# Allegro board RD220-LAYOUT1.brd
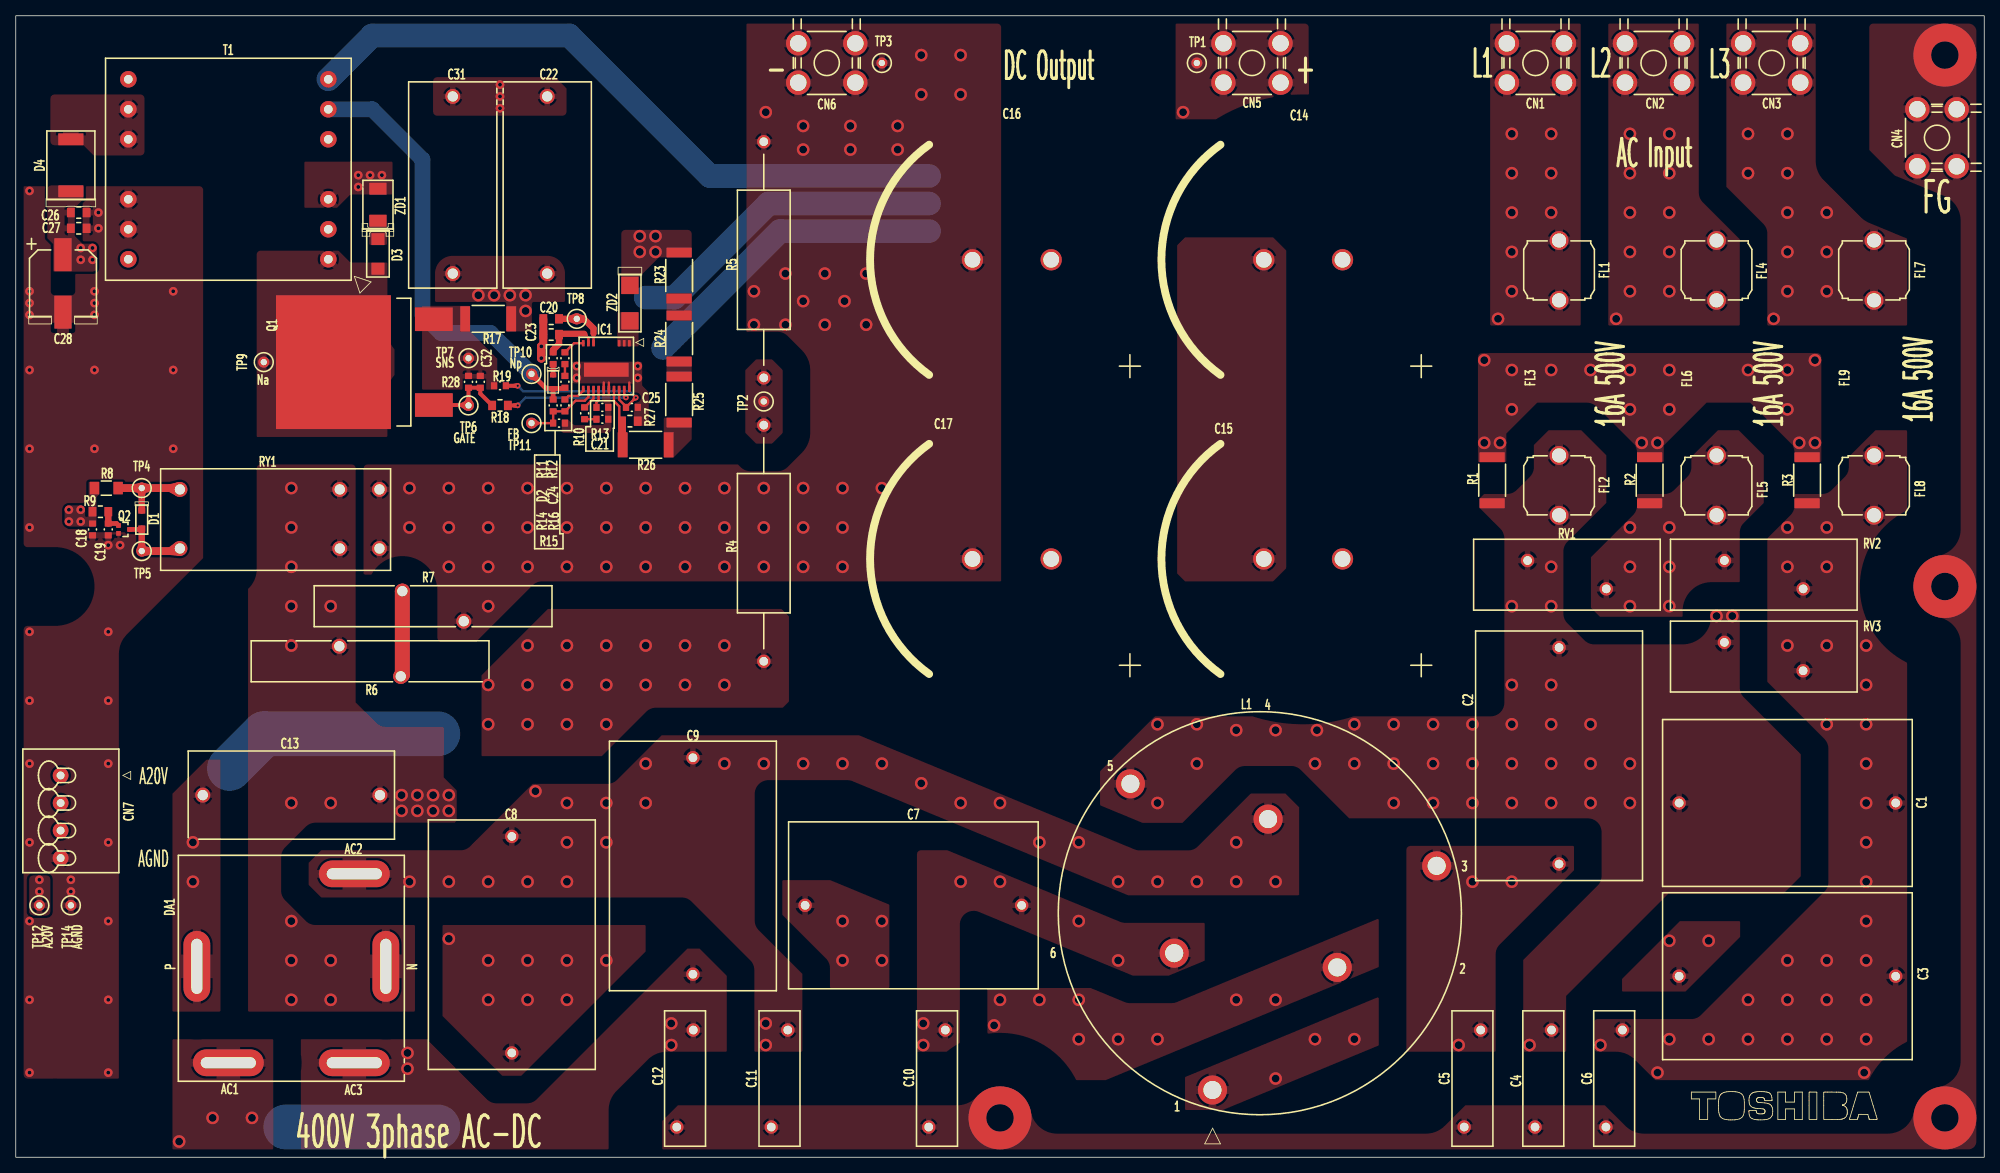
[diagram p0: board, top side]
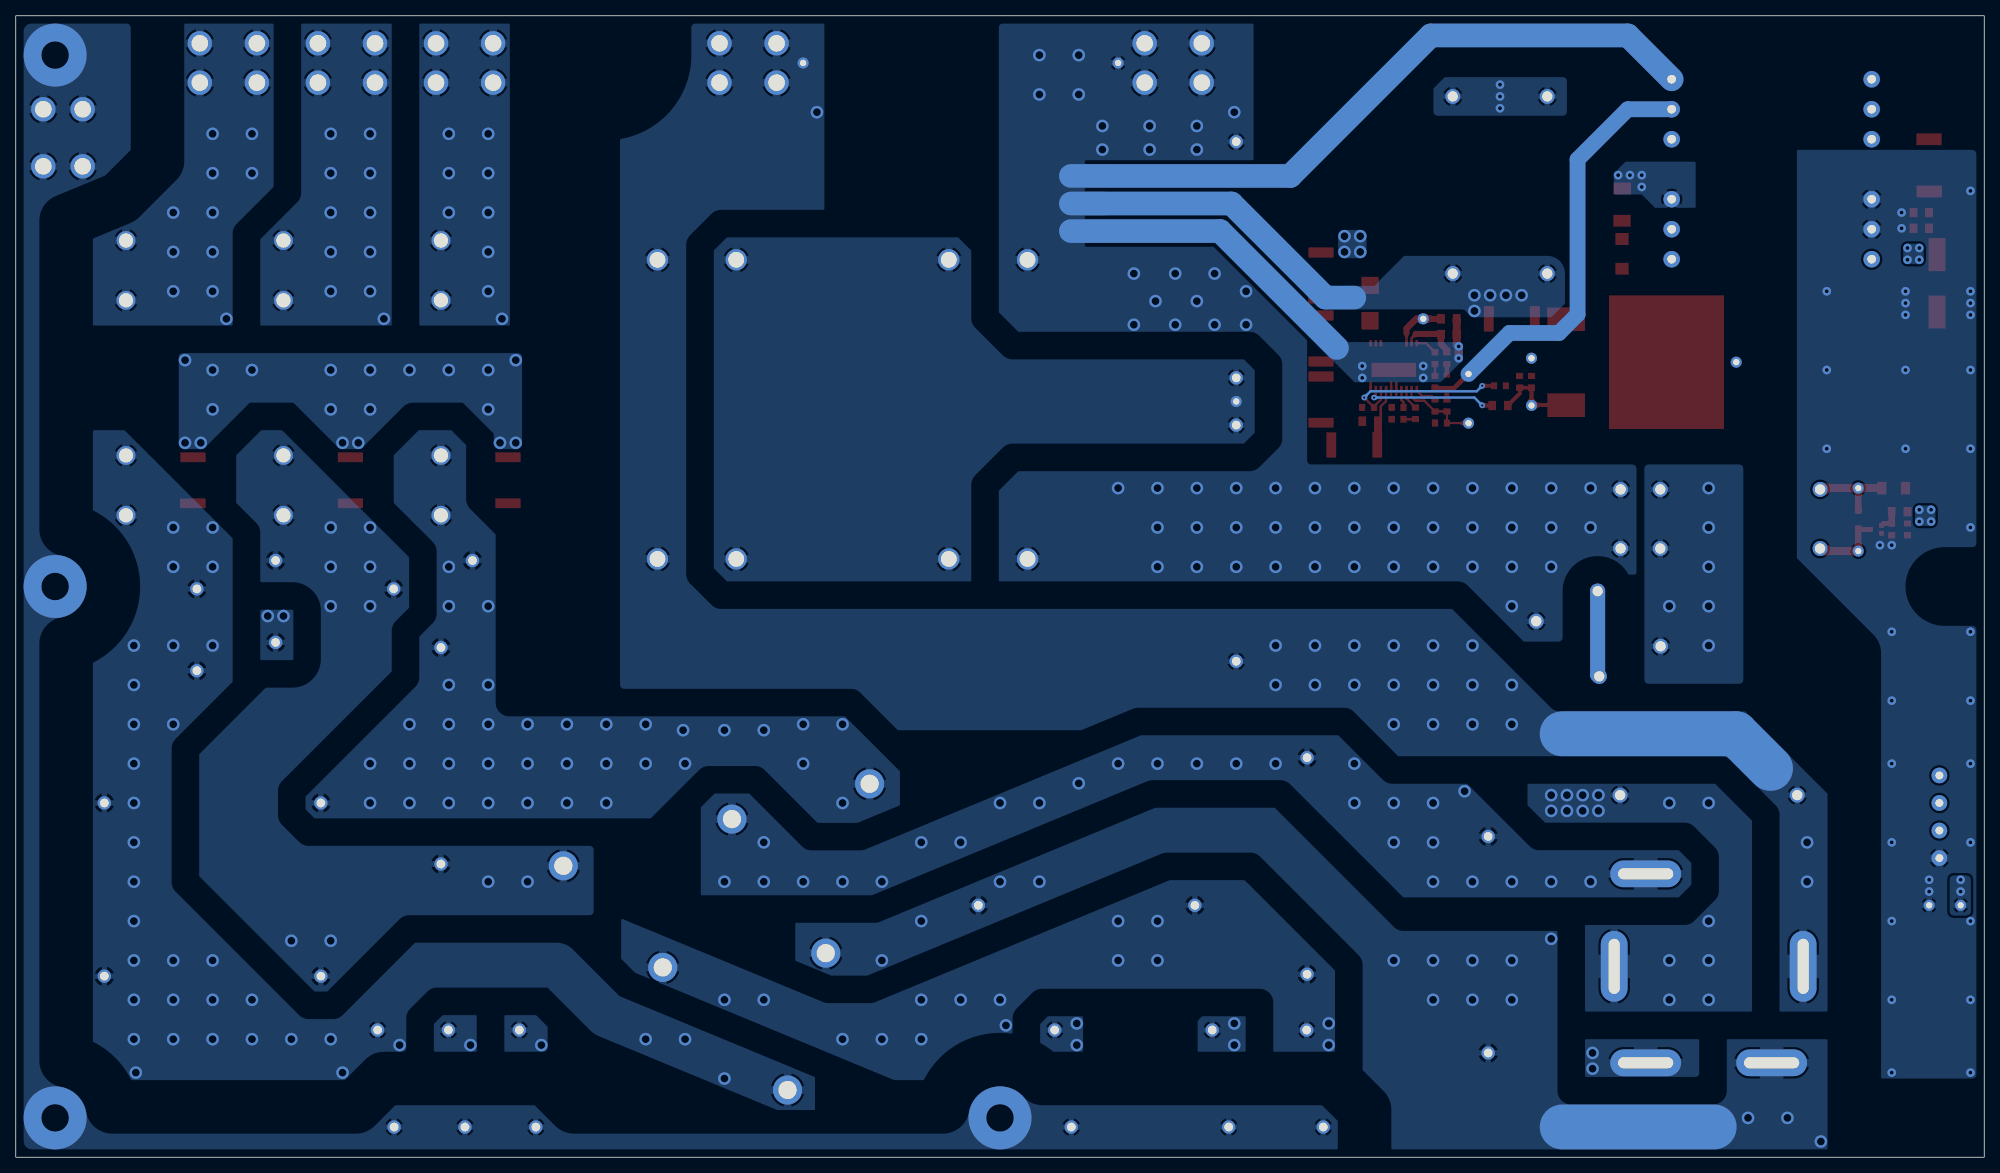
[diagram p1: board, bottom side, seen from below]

Outline 250 x 145 mm; copper layers: TOP, CONDUCTIVE2, CONDUCTIVE3, BOTTOM. Coordinates in mm from the lower left corner of the outline.
Outline path: rectangle 0,0 250,145

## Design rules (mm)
constraint set DEFAULT: 

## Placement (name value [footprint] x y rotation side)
C1  -  [TA_C0006DD]  225 45 180 top
C2  -  [TA_C0006DD]  196 51 90 top
C3  -  [TA_C0006DD]  225 23 180 top
C4  -  [TA_C0001DD]  194 10 90 top
C5  -  [TA_C0001DD]  185 10 90 top
C6  -  [TA_C0001DD]  203 10 90 top
C7  -  [TA_C0006DD]  114 32 0 top
C8  -  [TA_C0006DD]  63 27 270 top
C9  -  [TA_C0006DD]  86 37 90 top
C10  -  [TA_C0001DD]  117 10 90 top
C11  -  [TA_C0001DD]  97 10 90 top
C12  -  [TA_C0001DD]  85 10 90 top
C13  -  [TA_C0005DD]  35 46 180 top
C14  -  [TA_CE0001DD]  163.5 114 180 top
C15  -  [TA_CE0001DD]  163.5 76 180 top
C16  -  [TA_CE0001DD]  126.5 114 180 top
C17  -  [TA_CE0001DD]  126.5 76 180 top
C18  -  [TA_C0001RR]  9.75 79.75 90 top
C19  -  [TA_C0001RR]  11.75 79.75 90 top
C20  -  [TA_C0002RR]  68 106.5 0 top
C21  -  [TA_C0001RR]  74.5 93.75 180 top
C22  -  [TA_C0005DD]  67.5 123.5 90 top
C23  -  [TA_C0002RR]  68 104.5 0 top
C24  -  [TA_C0001RR]  69.75 98.5 270 top
C25  -  [TA_C0001RR]  78.25 95.25 180 top
C26  -  [TA_C0002RR]  8 120 180 top
C27  -  [TA_C0002RR]  8 118 180 top
C28  -  [TA_CE0002RR]  6 111 270 top
C31  -  [TA_C0005DD]  55.5 123.5 90 top
C32  -  [TA_C0001RR]  59 98.5 270 top
CN1  -  [TA_CN0004DD_OT_005_OT_006_]  193 139 90 top
CN2  -  [TA_CN0004DD_OT_005_OT_006_]  208 139 90 top
CN3  -  [TA_CN0004DD_OT_005_OT_006_]  223 139 90 top
CN4  -  [TA_CN0004DD_OT_005_OT_006_]  244 129.5 0 top
CN5  -  [TA_CN0004DD_OT_005_OT_006_]  157 139 90 top
CN6  -  [TA_CN0004DD_OT_005_OT_006_]  103 139 90 top
CN7  -  [TA_CN0002DD]  7 44 270 top
D1  -  [TA_D0002RR]  16 81 270 top
D2  -  [TA_D0001RR]  68.25 98.5 270 top
D3  -  [TA_D0005RR]  46 114.75 270 top
D4  -  [TA_D0006RR]  7 126 90 top
DA1  -  [TA_DA0001DD]  35 24 270 top
FL1  -  [TA_FL0001DD]  196 99 270 top
FL2  -  [TA_FL0001DD]  196 99 90 top
FL4  -  [TA_FL0001DD]  216 99 270 top
FL5  -  [TA_FL0001DD]  216 99 90 top
FL7  -  [TA_FL0001DD]  236 99 270 top
FL8  -  [TA_FL0001DD]  236 99 90 top
IC1  -  [TA_IC0002RR_70]  75 100.5 180 top
L1  -  [TA_L0001DD]  158 31 180 top
NOREF  -  []  5 5 0 top
NOREF#2  -  []  5 72.5 0 top
NOREF#3  -  []  175 140 0 top
NOREF#4  -  []  5 140 0 top
NOREF#5  -  []  212.8 4.8 0 top
Q1  -  [TA_FET0003RR]  44.5 101 90 top
Q2  -  [TA_Q0001RR]  13.75 79.75 270 top
R1  -  [TA_R0007RR]  187.5 86 270 top
R2  -  [TA_R0007RR]  207.5 86 270 top
R3  -  [TA_R0007RR]  227.5 86 270 top
R4  -  [TA_R0001DD]  95 78 270 top
R5  -  [TA_R0001DD]  95 114 270 top
R6  -  [TA_TH0001DD]  45 63 0 top
R7  -  [TA_TH0001DD]  53 70 0 top
R8  -  [TA_R0004RR]  11.5 85 0 top
R9  -  [TA_R0003RR]  10.75 82 180 top
R10  -  [TA_R0005RR]  72.25 94.5 270 top
R11  -  [TA_R0005RR]  68.25 101.5 270 top
R12  -  [TA_R0005RR]  69.75 101.5 90 top
R13  -  [TA_R0005RR]  74.5 95.25 0 top
R14  -  [TA_R0005RR]  68.25 95.5 270 top
R15  -  [TA_R0005RR]  69 93.25 0 top
R16  -  [TA_R0005RR]  69.75 95.5 90 top
R17  -  [TA_R0007RR]  60 106.5 0 top
R18  -  [TA_R0003RR]  61.5 95.5 0 top
R19  -  [TA_R0005RR]  61.5 98 0 top
R23  -  [TA_R0007RR]  84.25 112 270 top
R24  -  [TA_R0007RR]  84.25 104 270 top
R25  -  [TA_R0007RR]  84.25 96.25 270 top
R26  -  [TA_R0007RR]  80 90.5 180 top
R27  -  [TA_R0003RR]  78 93.5 0 top
R28  -  [TA_R0005RR]  57.5 98.5 90 top
RV1  -  [TA_RV0002DD]  197 74 180 top
RV2  -  [TA_RV0002DD]  222 74 180 top
RV3  -  [TA_RV0002DD]  222 63.6 180 top
RY1  -  [TA_RY0001DD]  33 81 0 top
T1  -  [TA_T0002DD]  27 125.5 90 top
TP1  -  [TA_TP0001DD]  150 139 0 top
TP2  -  [TA_TP0001DD]  95 96 0 top
TP3  -  [TA_TP0001DD]  110 139 0 top
TP4  -  [TA_TP0001DD]  16 85 90 top
TP5  -  [TA_TP0001DD]  16 77 90 top
TP6  -  [TA_TP0001DD]  57.5 95.5 180 top
TP7  -  [TA_TP0001DD]  57.5 101.5 180 top
TP8  -  [TA_TP0001DD]  71.25 106.5 180 top
TP9  -  [TA_TP0001DD]  31.5 101 90 top
TP10  -  [TA_TP0001DD]  65.5 99.5 180 top
TP11  -  [TA_TP0001DD]  65.5 93.25 180 top
TP12  -  [TA_TP0001DD]  3 32 90 top
TP14  -  [TA_TP0001DD]  7 32 90 top
ZD1  -  [TA_D0004RR]  46 121 90 top
ZD2  -  [TA_D0007RR]  78 108.5 270 top

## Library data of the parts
C1-C3 C7-C9 = PHE844RF7100MR30L2
C4-C6 C10-C12 = VKP472MCQEF0KR
C13 C22 C31 = PHE840EY7100MD16R06L2
C14-C17 = 400MXH1200MEFCSN35X60
C18 C19 = C1608X5R1V475K080AC
C20 C23 = GRM21BC71H475KE11L
C21 = C1608X7R1H224K080AE
C24 C32 = C1608C0G1H470J080AA
C25 = CGA3E2X7R1H102K080AA
C26 C27 = GRM21BR61H106ME43L
C28 = EMVH350ARA101MHA0G
CN1-CN6 = OT-005
CN7 = 1984989
D1 = CUS10F40_H3F
D2 = BAS516_L3F
D3 = US1M-E3/61T
D4 = VSSC520S-M3/57T
DA1 = VS-36MT120
FL1 FL2 FL4 FL5 FL7 FL8 = 8040.0001
IC1 = LT8316IFE*PBF
L1 = T60405S6123X317
Q1 = APT14M120S
Q2 = 2SC4738-Y_LF
R1-R3 = 3521220KFT
R4 R5 = ROX5SSJ56K
R6 R7 = SL32_5R020
R8 = ERJ8ENF62R0V
R9 = ERJ6ENF3301V
R10 R12 R28 = RK73H1JTTD1002D
R11 = RK73H1JTTD10R0F
R13 = RK73H1JTTD8202F
R14 = RK73H1JTTD2202F
R15 = RK73H1JTTD3001F
R16 = RK73H1JTTD1203F
R17 = RLP73N3AR068FTDF
R18 = RK73G2ATTD33R0F
R19 = RK73H1JTTD1000F
R23-R26 = CRGP2512F68K
R27 = ERJ6ENF6800V
RV1-RV3 = TND20SV821KB00AAA0
RY1 = RTH34024WG
T1 = 11328-T080
TP1-TP12 TP14 = Test_Land
ZD1 = SMBJ188D-M3/I
ZD2 = BZG03C200-M3-08

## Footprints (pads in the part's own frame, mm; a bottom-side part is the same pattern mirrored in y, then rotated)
TA_C0001DD
  round 1.7 hole 1.1: 1(-6.161,1.05) 2(6.161,-1.05)
TA_C0001RR
  custom 0.2x0.2 smd: 1(-0.75,0) 2(0.75,0)
TA_C0002RR
  custom 0.25x0.25 smd: 1(-1,0) 2(1,0)
TA_C0005DD
  round 1.9 hole 1.3: 1(-11.25,0) 2(11.25,0)
TA_C0006DD
  round 1.7 hole 1.1: 1(-13.75,0) 2(13.75,0)
TA_CE0001DD
  round 2.7 hole 2: 1(5,0) 2(-5,0)
TA_CE0002RR
  custom 0.55x0.55 smd: 1(3.65,0) 2(-3.65,0)
TA_CN0002DD
  round 2 hole 1: 1(-4.5,-1.3) 2(-1,-1.3) 3(2.5,-1.3) 4(6,-1.3)
TA_CN0004DD_OT_005_OT_006_
  round 3.1 hole 2.1: 1(-2.5,-3.625) 2(2.5,-3.625) 3(2.5,3.625) 4(-2.5,3.625)
TA_D0001RR
  custom 0.15x0.15 smd: A(0.85,0) C(-0.85,0)
TA_D0002RR
  custom 0.2x0.2 smd: A(1.15,0) C(-1.15,0)
TA_D0004RR
  custom 0.38x0.38 smd: A(2.035,0) C(-2.035,0)
TA_D0005RR
  custom 0.38x0.38 smd: A(1.88,0) C(-1.88,0)
TA_D0006RR
  custom 0.38x0.38 smd: A(3.305,0) C(-3.305,0)
TA_D0007RR
  custom 0.55x0.55 smd: A(2.25,0) C(-2.25,0)
TA_DA0001DD
  oval 3.4x9 hole 1.4x7: AC1(12,-8) AC2(-12,8) AC3(12,8)
  oval 9x3.4 hole 7x1.4: N(-0.25,12) P(-0.25,-12)
TA_FET0003RR
  custom 3.65x3.65 smd: D(0,4.15)
  custom 0.75x0.75 smd: G(-5.45,-8.6) S(5.45,-8.6)
TA_FL0001DD
  round 2.4 hole 1.8: 1(-17.45,0) 2(-9.85,0)
TA_IC0002RR_70
  custom 0.087x0.087 smd: 1(-2.925,-2.9) 2(-2.275,-2.9) 3(-1.625,-2.9) 8(1.625,-2.9) 9(2.275,-2.9) 10(2.925,-2.9) 11(2.925,2.9) 12(2.275,2.9) 13(1.625,2.9) 14(0.975,2.9) 15(0.325,2.9) 16(-0.325,2.9) 17(-0.975,2.9) 18(-1.625,2.9) 19(-2.275,2.9) 20(-2.925,2.9)
  custom 0.445x0.445 smd: 21(0,0.47)
TA_L0001DD
  round 3.7 hole 2.3: 1(6.018,22.458) 2(-9.83,6.883) 3(-22.458,-6.018) 4(-1.046,-11.954) 5(16.44,-16.44) 6(10.876,5.071)
TA_Q0001RR
  custom 0.15x0.15 smd: B(-0.5,-0.7) C(0,0.7) E(0.5,-0.7)
TA_R0001DD
  round 1.7 hole 1.1: 1(-15,0) 2(15,0)
TA_R0003RR
  custom 0.25x0.25 smd: 1(-1,0) 2(1,0)
TA_R0004RR
  custom 0.3x0.3 smd: 1(-1.5,0) 2(1.5,0)
TA_R0005RR
  custom 0.2x0.2 smd: 1(-0.75,0) 2(0.75,0)
TA_R0007RR
  custom 0.312x0.312 smd: 1(-2.925,0) 2(2.925,0)
TA_RV0002DD
  round 1.7 hole 1.1: 1(-5,1.8) 2(5,-1.8)
TA_RY0001DD
  round 1.9 hole 1.3: 11-1(8.15,3.83) 11-2(8.15,-3.67) 14-1(13.19,3.83) 14-2(13.19,-3.67) A1(-12.15,3.83) A2(-12.15,-3.67)
TA_T0002DD
  round 2.1 hole 1.1: 1(-11.43,-12.7) 2(-7.62,-12.7) 3(-3.81,-12.7) 4(3.81,-12.7) 5(7.62,-12.7) 6(11.43,-12.7) 7(11.43,12.7) 8(7.62,12.7) 9(3.81,12.7) 10(-3.81,12.7) 11(-7.62,12.7) 12(-11.43,12.7)
TA_TH0001DD
  round 1.9 hole 1.3: 1(-3.9,1.91) 2(3.9,-1.91)
TA_TP0001DD
  round 1.4 hole 0.8: 1(0,0)

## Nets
GND_A: C18.1 C19.1 C26.1 C27.1 C28.1 CN7.4 Q2.E T1.10 T1.11 TP14.1
GND_DC: C16.1 C17.1 C20.1 C21.1 C22.1 C23.1 C25.1 C31.1 CN6.1 CN6.2 CN6.3 CN6.4 IC1.15 IC1.16 IC1.20 IC1.21 R5.1 R7.2 R13.2 R15.2 R17.2 R27.2 RY1.14-1 RY1.14-2 T1.6 TP3.1
GND_F: C4.1 C5.1 C6.1 C10.1 C11.1 C12.1 CN4.1 CN4.2 CN4.3 CN4.4
VDD20_A: C18.2 C26.2 C27.2 C28.2 CN7.1 D4.C R8.1 R9.2 TP12.1
L1: CN1.1 CN1.2 CN1.3 CN1.4 FL1.1 FL1.2
L1F: C1.2 C2.2 C4.2 FL2.1 FL2.2 L1.5 R1.2 RV1.2 RV3.2
L1R: C7.2 C8.2 C10.2 DA1.AC1 L1.6
L2: CN2.1 CN2.2 CN2.3 CN2.4 FL4.1 FL4.2
L2F: C2.1 C3.2 C5.2 FL5.1 FL5.2 L1.3 R2.2 RV1.1 RV2.2
L2R: C8.1 C9.2 C11.2 DA1.AC2 L1.4
L3: CN3.1 CN3.2 CN3.3 CN3.4 FL7.1 FL7.2
L3F: C1.1 C3.1 C6.2 FL8.1 FL8.2 L1.1 R3.2 RV2.1 RV3.1
L3R: C7.1 C9.1 C12.2 DA1.AC3 L1.2
M: C14.1 C15.1 C16.2 C17.2 R4.1 R5.2 TP2.1
RDIS: R1.1 R2.1 R3.1
SIGN0021: C20.2 IC1.8 TP8.1
SIGN0023: IC1.13 R10.1
SIGN0024: C21.2 R10.2
SIGN0029: C23.2 IC1.9 R11.1
SIGN00121: R6.2 R7.1
SIGN00122: C13.1 DA1.N R6.1 RY1.11-1 RY1.11-2
SIGN00123: D1.C R8.2 RY1.A1 TP4.1
SIGN00124: D1.A Q2.C RY1.A2 TP5.1
SIGN00125: C19.2 Q2.B R9.1
SIGN00210: D2.C R11.2
SIGN00211: C24.2 D2.A R14.1 T1.5 TP10.1
SIGN00212: IC1.10 R12.2
SIGN00213: C24.1 R12.1
SIGN00214: IC1.14 R13.1
SIGN00218: IC1.11 R16.2
SIGN00219: IC1.12 R14.2 R15.1 R16.1 TP11.1
SIGN00220: C32.1 Q1.S R17.1 R19.1 R28.2 TP7.1
SIGN00222: IC1.19 R18.2
SIGN00223: C25.2 IC1.18 R19.2
SIGN00224: D3.C ZD1.C
SIGN00225: D3.A Q1.D T1.1 TP9.1
SIGN00226: C32.2 Q1.G R18.1 R28.1 TP6.1
SIGN00227: D4.A T1.8 T1.9
SIGN00230: IC1.1 IC1.2 IC1.3 ZD2.A
SIGN00231: R25.2 R26.1
SIGN00232: R23.2 R24.1
SIGN00233: R24.2 R25.1
SIGN00234: IC1.17 R26.2 R27.1
VP_DC: C13.2 C14.2 C15.2 C22.2 C31.2 CN5.1 CN5.2 CN5.3 CN5.4 DA1.P R4.2 R23.1 T1.3 TP1.1 ZD1.A ZD2.C

Pads without a net: CN7 2 3; T1 2 4 7 12

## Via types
v1: diameter 0.7, hole 0.3, TOP to BOTTOM, 4 vias
v2: diameter 1.6, hole 1, TOP to BOTTOM, 305 vias
v3: diameter 1.1, hole 0.5, TOP to BOTTOM, 58 vias
v4: diameter 8, hole 3.5, TOP to BOTTOM, 4 vias

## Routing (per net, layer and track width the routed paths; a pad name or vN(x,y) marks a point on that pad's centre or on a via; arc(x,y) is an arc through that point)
GND_A:
  vias: v3(1.75,122.75) v3(1.75,110) v3(1.75,108.5) v3(1.75,107) v3(1.75,100) v3(1.75,90) v3(1.75,80) v3(1.75,66.75) v3(1.75,58) v3(1.75,50) v3(1.75,40) v3(1.75,30) v3(1.75,20) v3(1.75,10.75) v3(7,35.25) v3(7,33.75) v3(10,110) v3(10,108.5) v3(10,107) v3(10,100) v3(10,90) v3(10.5,120) v3(10.5,118) v3(11.75,77.75) v3(11.75,66.75) v3(11.75,58) v3(11.75,50) v3(11.75,40) v3(11.75,30) v3(11.75,20) v3(11.75,10.75) v3(13.25,77.75) v3(20,110) v3(20,100) v3(20,90)
GND_DC: length 176
  TOP w0.3: 74.67,96.8 IC1.15 74.67,98.4 ; 75.33,98.4 IC1.16 75.33,96.8 ; IC1.20 77.92,98.4
  TOP w1: C20.1 C23.1 67,103.25 v3(66.75,103)
  TOP w1.1: v3(66.75,101.5) v3(66.75,103)
  BOTTOM w3: 82.2,102.8 97.05,117.65 116,117.65 ; 80,109.2 83.65,109.2 95.6,121.15 116,121.15 ; T1.6 45.27,142.5 70.29,142.5 88.14,124.65 116,124.65
  vias: v2(50,85) v2(50,80) v2(55,85) v2(55,80) v2(55,75) v2(58.75,109.5) v2(60,85) v2(60,80) v2(60,75) v2(60,70) v2(60.75,109.5) v2(62.75,109.5) v2(64.75,109.5) v2(64.75,107.5) v2(65,85) v2(65,80) v2(65,75) v2(70,85) v2(70,80) v2(70,75) v2(75,85) v2(75,80) v2(75,75) v2(80,85) v2(80,80) v2(80,75) v2(85,85) v2(85,80) v2(85,75) v2(90,85) v2(90,80) v2(90,75) v2(93.75,110) v2(93.75,105.75) v2(95,85) v2(95,80) v2(95,75) v2(95.25,132.75) v2(97.75,112.25) v2(97.75,105.75) v2(100,131) v2(100,128) v2(100,108.75) v2(100,85) v2(100,80) v2(100,75) v2(102.75,112.25) v2(102.75,105.75) v2(105,85) v2(105,80) v2(105,75) v2(105.25,108.75) v2(106,131) v2(106,128) v2(108,112.25) v2(108,105.75) v2(110,85) v2(112,131) v2(112,128) v2(115,140) v2(115,135) v2(120,140) v2(120,135) v3(71.25,100.5) v3(71.25,99) v3(79,100.5) v3(79,99)
GND_F:
  vias: v4(125,5) v4(245,140) v4(245,72.5) v4(245,5)
VDD20_A: length 75.9
  CONDUCTIVE3 w1.5: 8.1,83.89 8.1,112.36 ; 3.85,36.66 3.85,46.65 CN7.1 5.7,63.94 11.55,69.79 11.55,75.21 7.49,79.27
  vias: v3(3,35.25) v3(3,33.75) v3(6.75,82.25) v3(6.75,80.75) v3(8.25,115.5) v3(8.25,114) v3(8.25,82.25) v3(8.25,80.75) v3(9.75,115.5) v3(9.75,114)
L1:
  vias: v2(188.25,106.5) v2(190,130) v2(190,125) v2(190,120) v2(190,115) v2(190,110) v2(195,130) v2(195,125) v2(195,120)
L1F:
  vias: v2(145,55) v2(145,45) v2(150,55) v2(150,50) v2(155,54.25) v2(160,54.25) v2(165,50) v2(165.25,54.25) v2(170,55) v2(170,50) v2(175,55) v2(175,50) v2(175,45) v2(180,55) v2(180,50) v2(180,45) v2(185,55) v2(185,50) v2(185,45) v2(190,70) v2(190,60) v2(190,55) v2(190,50) v2(190,45) v2(192.25,14.25) v2(195,75) v2(195,70) v2(195,60) v2(195,55) v2(195,50) v2(195,45) v2(200,55) v2(200,50) v2(200,45) v2(205,50) v2(205,45) v2(216,68.75) v2(218,68.75)
L1R: length 38.4
  CONDUCTIVE3 w5.7: 34.5,3.85 53.6,3.85
  BOTTOM w5.7: 34.3,3.85 53.6,3.85
  vias: v2(20.75,2) v2(25,5) v2(30,5) v2(55,27.75) v2(60,25) v2(60,20) v2(65,25) v2(65,20) v2(70,25) v2(70,20) v2(75,25) v2(115.25,17) v2(115.25,14.25) v2(120,35) v2(125,35) v2(135,30) v2(140,25)
L2:
  vias: v2(203.25,106.5) v2(205,130) v2(205,125) v2(205,120) v2(205,115) v2(205,110) v2(210,130) v2(210,125) v2(210,120) v2(210,115) v2(210,110)
L2F:
  vias: v2(183.25,14.25) v2(185,35) v2(190,35) v2(205,80) v2(205,75) v2(205,70) v2(210,80) v2(210,75) v2(210,70) v2(210,27.5) v2(215,27.5)
L2R:
  vias: v2(50,35) v2(55,35) v2(60,35) v2(65,35) v2(66,46.5) v2(70,45) v2(70,40) v2(70,35) v2(75,45) v2(75,40) v2(80,50) v2(80,45) v2(90,50) v2(95,50) v2(95.25,17) v2(95.25,14.25) v2(100,50) v2(105,50) v2(110,50) v2(115,47.5) v2(120,45) v2(125,45) v2(130,40) v2(135,40) v2(140,35) v2(145,35) v2(150,35) v2(155,40) v2(155,35) v2(160,35)
L3:
  vias: v2(220,130) v2(220,125) v2(223.25,106.5) v2(225,130) v2(225,125) v2(225,120) v2(225,115) v2(225,110) v2(230,120) v2(230,115) v2(230,110)
L3F:
  vias: v2(160,10) v2(165,15) v2(170,15) v2(201.25,14.25) v2(208.5,10.75) v2(210,15) v2(215,15) v2(220,20) v2(220,15) v2(225,80) v2(225,75) v2(225,65) v2(225,25) v2(225,20) v2(225,15) v2(230,80) v2(230,75) v2(230,65) v2(230,55) v2(230,25) v2(230,20) v2(230,15) v2(234.75,10.75) v2(235,65) v2(235,60) v2(235,55) v2(235,50) v2(235,45) v2(235,40) v2(235,35) v2(235,30) v2(235,25) v2(235,20) v2(235,15)
L3R:
  vias: v2(49.75,13.25) v2(49.75,11.25) v2(83.25,17) v2(83.25,14.25) v2(105,30) v2(105,25) v2(110,30) v2(110,25) v2(124.25,16.75) v2(125,20) v2(130,20) v2(135,20) v2(135,15) v2(140,15) v2(145,15) v2(155,20) v2(160,20)
RDIS:
  vias: v2(186.5,101.25) v2(186.5,90.75) v2(188.5,90.75) v2(190,100) v2(190,95) v2(195,100) v2(200,100) v2(205,100) v2(205,95) v2(206.5,90.75) v2(208.5,90.75) v2(210,100) v2(210,95) v2(220,100) v2(225,100) v2(225,95) v2(226.5,90.75) v2(228.5,101.25) v2(228.5,90.75)
SIGN0021: length 6.8
  TOP w0.3: IC1.8 73.38,104.72
  TOP w0.8: 73.38,104.72 73.38,105.28 72.15,106.5 TP8.1 C20.2
SIGN0023: length 2.8
  TOP w0.3: R10.1 73.38,96.38 IC1.13
SIGN0024: length 1.5
  TOP w0.3: R10.2 C21.2
SIGN0029: length 7.3
  TOP w0.3: IC1.9 72.72,104.05 72.17,104.6
  TOP w0.8: 72.17,104.6 69,104.6 C23.2 69,103.31 68.25,102.56 R11.1
SIGN00121: length 43.6
  TOP w1.9: R6.2 49.1,61.29 R7.1
  CONDUCTIVE2 w1.9: R6.2 49.1,61.29 R7.1
  CONDUCTIVE3 w1.9: R7.1 49.1,61.29 R6.2
  BOTTOM w1.9: R6.2 49.1,61.29 R7.1
SIGN00122:
  vias: v2(35,85) v2(35,80) v2(35,75) v2(35,70) v2(35,65) v2(35,45) v2(35,30) v2(35,25) v2(35,20) v2(40,70) v2(40,45) v2(40,25) v2(40,20) v2(49,46) v2(49,44) v2(51,46) v2(51,44) v2(53,46) v2(53,44) v2(55,46) v2(55,44)
SIGN00123: length 10.7
  TOP w0.8: D1.C TP4.1
  TOP w1: R8.2 TP4.1 19.63,85 RY1.A1
SIGN00124: length 9.3
  TOP w0.6: D1.A 15.9,79.75 Q2.C
  TOP w0.8: D1.A TP5.1
  TOP w1: TP5.1 19.66,77 RY1.A2
SIGN00125: length 2.9
  TOP w0.6: Q2.B 12.8,80.5 C19.2
  TOP w0.8: C19.2 R9.1
SIGN00210: length 1.4
  TOP w0.6: R11.2 D2.C
SIGN00211: length 57.7
  TOP w0.6: C24.2 69.65,97.65 D2.A ; R14.1 D2.A ; D2.A 67.35,97.65 TP10.1
  BOTTOM w2: T1.5 45.27,133.12 51.65,126.74 51.65,107.06 54.01,104.7 60.3,104.7 TP10.1
SIGN00212: length 2.8
  TOP w0.3: R12.2 70.9,103.4 IC1.10
SIGN00213: length 1.5
  TOP w0.3: C24.1 R12.1
SIGN00214: length 2.5
  TOP w0.3: IC1.14 74.03,96.18 73.75,95.9 R13.1
SIGN00218: length 3
  TOP w0.3: IC1.11 72.08,97.38 71.39,96.7 70.2,96.7 R16.2
SIGN00219: length 10.5
  TOP w0.3: TP11.1 R15.1 R14.2 R16.1 71.1,96.1 72.25,96.1 72.72,96.57 IC1.12
SIGN00222: length 16.6
  TOP w0.3: v1(77.5,96.5) 77.28,96.9 IC1.19
  TOP w0.5: R18.2 v1(63.75,95.5)
  BOTTOM w0.3: v1(63.75,95.5) 64.75,96.5 v1(77.5,96.5)
SIGN00223: length 21.6
  TOP w0.3: IC1.18 76.62,96.24 77.5,95.37 C25.2 v1(78.75,96.5)
  TOP w0.5: R19.2 v1(63.75,98)
  BOTTOM w0.3: v1(78.75,96.5) 77.95,97.3 64.45,97.3 v1(63.75,98)
SIGN00226: length 11
  TOP w0.5: R18.1 59,97 C32.2 R28.1 TP6.1 56.59,95.55 Q1.G
SIGN00234: length 7.6
  TOP w0.3: IC1.17 75.97,96.05 76.65,95.37 76.65,93.85 R27.1
  TOP w1: R26.2 77,90.58 R27.1
VP_DC: length 197.6
  CONDUCTIVE2 w3: 85.05,118.6 117.19,118.6 120.44,121.85 150,121.85 ; 150,125.35 118.99,125.35 115.74,122.1 75.15,122.1
  CONDUCTIVE3 w5.7: 52.2,53.79 31.54,53.79 27.14,49.39
  BOTTOM w5.7: 53.6,53.79 31.54,53.79 27.14,49.39
  vias: v2(22.5,40) v2(22.5,35) v2(60,60) v2(60,55) v2(65,65) v2(65,60) v2(65,55) v2(70,65) v2(70,60) v2(70,55) v2(75,65) v2(75,60) v2(75,55) v2(79.25,117) v2(79.25,115) v2(80,65) v2(80,60) v2(81.25,117) v2(81.25,115) v2(85,65) v2(85,60) v2(90,65) v2(90,60) v2(148.25,132.75) v3(43.5,124.75) v3(43.5,123.25) v3(45,124.75) v3(46.5,124.75) v3(61.5,136.25) v3(61.5,134.75) v3(61.5,133.25)

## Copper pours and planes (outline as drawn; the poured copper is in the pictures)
GND_A on TOP: 3.7,116.81 3.73,116.64 3.83,116.49 4.41,115.92 4.44,115.87 4.45,115.81 4.45,110 4.6,109.65 4.95,109.5 7.05,109.5 7.4,109.65 7.55,110 7.55,112.05 7.59,112.16 7.7,112.2 9.8,112.2 10.37,112.43 10.6,113 10.6,115.5 10.35,116.1 9.75,116.35 8.66,116.35 8.61,116.36 8.56,116.39 8.54,116.41 8.51,116.46 8.5,116.51 8.5,121.11 8.51,121.17 8.54,121.22 8.77,121.44 8.87,121.59 8.9,121.76 8.9,123.2 8.94,123.31 9.05,123.35 23.3,123.35 23.65,123.2 23.8,122.85 23.8,76.17 23.79,76.11 23.76,76.06 14.1,66.4 13.71,65.95 13.42,65.44 13.22,64.88 13.11,64.3 13.1,64 13.1,10.14 13.06,10.03 12.95,9.99 5.32,9.99 5,10 4.68,9.99 1.5,9.99 1.25,10.06 1.07,10.24 1,10.49 1,67 1.07,67.25 1.25,67.43 1.5,67.5 5,67.5 10,72.5 5,77.5 1.5,77.5 1.15,77.65 1,78 1,123.2 1.04,123.31 1.15,123.35 3.58,123.35 3.7,123.29 3.73,123.16 3.71,123.06 3.7,122.95 ; 32 cut-outs
GND_A on BOTTOM: 1.5,77.5 1.25,77.57 1.07,77.75 1,78 1,127.46 1.07,127.71 1.25,127.89 1.5,127.96 23.65,127.96 23.76,127.92 23.8,127.81 23.8,76.17 23.79,76.11 23.76,76.06 14.1,66.4 13.36,65.3 13.1,64 13.1,10.15 13.06,10.04 12.95,10 1.5,10 1.25,10.07 1.07,10.25 1,10.5 1,67 1.07,67.25 1.25,67.43 1.5,67.5 5,67.5 10,72.5 5,77.5 ; 27 cut-outs
GND_A on CONDUCTIVE2: 1.5,77.5 1.25,77.57 1.07,77.75 1,78 1,127.46 1.07,127.71 1.25,127.89 1.5,127.96 23.65,127.96 23.76,127.92 23.8,127.81 23.8,76.17 23.79,76.11 23.76,76.06 14.1,66.4 13.36,65.3 13.1,64 13.1,10.15 13.06,10.04 12.95,10 5.11,10 5,10 4.89,10 1.5,10 1.25,10.07 1.07,10.25 1,10.5 1,67 1.07,67.25 1.25,67.43 1.5,67.5 5,67.5 10,72.5 5,77.5 ; 27 cut-outs
GND_A on CONDUCTIVE3: 1,67 1.07,67.25 1.25,67.43 1.5,67.5 5,67.5 10,72.5 5,77.5 1.5,77.5 1.25,77.57 1.07,77.75 1,78 1,127.46 1.07,127.71 1.25,127.89 1.5,127.96 23.65,127.96 23.76,127.92 23.8,127.81 23.8,76.17 23.79,76.11 23.76,76.06 14.1,66.4 13.36,65.3 13.1,64 13.1,10.15 13.06,10.04 12.95,10 1.15,10 1.04,10.04 1,10.15 ; 20 cut-outs
GND_DC on TOP: 100.9,99.94 100.62,101.33 99.83,102.52 98.57,103.78 98.01,104.34 97.44,104.72 96.78,104.85 93.3,104.85 93.14,104.84 92.98,104.82 92.85,104.85 92.8,104.97 92.8,143.85 92.84,143.96 92.95,144 124.65,144 125,143.85 125.15,143.5 125.15,73.3 125.11,73.19 125,73.15 66.86,73.15 66.19,73.02 65.62,72.64 58.53,65.54 58.48,65.51 58.42,65.5 54.05,65.5 53.7,65.65 53.55,66 53.55,71.91 51.9,75.37 48.17,76.26 46.99,75.83 45.99,75.09 45.56,74.61 45.21,74.08 45.16,74.02 45.08,74 44.5,74 44.37,74.02 44.24,74.07 44.19,74.13 44.17,74.2 44.17,87.5 44.24,87.75 44.42,87.93 44.67,88 91.66,88 91.72,87.99 91.77,87.96 92.31,87.46 92.58,87.3 92.73,87.25 93.09,87.16 93.3,87.15 96.77,87.15 97.44,87.28 98.01,87.66 98.57,88.22 99.83,89.48 100.62,90.67 100.9,92.06 ; 44 cut-outs
GND_DC on TOP: 69.6,92 69.47,92.03 69.38,92.12 69.35,92.25 69.35,93.55 69.39,93.66 69.5,93.7 70.09,93.7 70.15,93.69 70.19,93.66 70.7,93.15 70.93,93.02 71.06,93 74.6,93 74.85,93.25 74.85,95.7 74.52,96.03 74.48,96.09 74.47,96.15 74.47,96.18 74.47,96.75 74.52,96.86 74.62,96.9 75.38,96.9 75.48,96.86 75.53,96.75 75.53,96.05 75.55,95.9 75.64,95.73 75.65,95.68 75.65,92.5 75.58,92.25 75.4,92.07 75.15,92
GND_DC on TOP: 53.25,112.19 53.25,112.2 53.91,113.84 55.55,114.5 55.56,114.5 67.44,114.5 67.45,114.5 69.09,113.84 69.75,112.2 69.75,112.19 69.75,108.8 69.71,108.69 69.6,108.65 65.8,108.65 65.67,108.62 65.58,108.53 65.55,108.4 65.55,105.05 65.51,104.94 65.4,104.9 62.45,104.9 62.34,104.94 62.3,105.05 62.3,108.4 62.23,108.58 62.05,108.65 53.4,108.65 53.29,108.69 53.25,108.8 ; 8 cut-outs
GND_DC on TOP: 78.65,92.9 78.54,92.94 78.5,93.05 78.5,94.64 78.51,94.7 78.54,94.74 78.6,94.8 78.6,95.65 78.61,95.71 78.67,95.78 78.71,95.8 78.96,95.88 79.38,96.67 78.63,97.14 78.5,97.17 78.45,97.29 78.45,97.95 78.4,98.12 78.28,98.25 78.1,98.3 70.95,98.3 70.83,98.33 70.73,98.42 70.7,98.55 70.7,100.9 70.74,101.01 70.85,101.05 79.3,101.05 79.42,101.02 79.52,100.92 79.55,100.8 79.55,98.03 80.36,97.23 80.39,97.18 80.4,97.12 80.4,93.05 80.36,92.94 80.25,92.9
GND_DC on BOTTOM: 66.24,101.29 66.2,101.5 66.2,103 66.36,103.39 66.75,103.55 80.83,103.55 82.28,105 82.39,105.05 82.5,105 84.41,103.09 84.45,102.99 84.41,102.88 80.02,98.49 79.97,98.46 79.91,98.45 69.25,98.45 69.04,98.49 68.86,98.61
GND_DC on BOTTOM: outline of 105 points within 44.17,65.5 125.15,144 ; 44 cut-outs
GND_DC on BOTTOM: 73.61,114.5 73.66,114.49 73.71,114.46 77.47,110.7 81,110.7 81.25,110.63 81.43,110.45 81.5,110.2 81.5,108.2 81.36,107.85 81.01,107.7 81.01,107.7 66.29,107.7 66.04,107.63 65.93,107.55 65.32,106.93 65.05,106.76 64.75,106.7 55.06,106.7 55,106.71 54.96,106.74 53.29,108.41 53.26,108.45 53.25,108.51 53.25,112.19 53.25,112.2 53.91,113.84 55.55,114.5 55.56,114.5 ; 8 cut-outs
GND_DC on CONDUCTIVE2: 92.8,143.85 92.84,143.96 92.95,144 124.65,144 125,143.85 125.15,143.5 125.15,130.5 125.11,130.39 125,130.35 118.99,130.35 117.08,129.97 115.46,128.89 113.71,127.14 113.66,127.11 113.61,127.1 92.95,127.1 92.84,127.14 92.8,127.25 ; 24 cut-outs
GND_DC on CONDUCTIVE2: outline of 83 points within 44.17,65.5 125.15,116.85 ; 19 cut-outs
GND_DC on CONDUCTIVE2, CONDUCTIVE3: 69.25,98.4 69.02,98.45 68.83,98.58 66.33,101.07 66.33,101.08 66.19,101.27 66.15,101.5 66.15,103 66.33,103.42 66.75,103.6 79.1,103.6 79.35,103.53 79.53,103.35 79.6,103.1 79.6,99 79.42,98.58 79,98.4
GND_DC on CONDUCTIVE2, CONDUCTIVE3: 53.25,112.19 53.25,112.2 53.91,113.84 55.55,114.5 55.56,114.5 67.39,114.5 67.41,114.5 69.09,113.84 69.75,112.16 69.75,112.14 69.75,110.31 69.74,110.25 69.71,110.21 67.24,107.74 67.2,107.71 67.14,107.7 66.29,107.7 66.04,107.63 65.93,107.55 65.32,106.93 65.05,106.76 64.75,106.7 53.4,106.7 53.29,106.74 53.25,106.85 ; 8 cut-outs
GND_DC on CONDUCTIVE3: 92.8,143.85 92.84,143.96 92.95,144 124.65,144 125,143.85 125.15,143.5 125.15,107.39 125.14,107.33 125.11,107.28 122.72,104.89 122.67,104.86 122.61,104.85 93.3,104.85 92.63,104.72 92.06,104.34 89.66,101.94 89.28,101.37 89.15,100.7 89.15,91.3 89.28,90.63 89.66,90.06 92.06,87.66 92.07,87.66 92.63,87.28 93.3,87.15 122.61,87.15 122.67,87.14 122.72,87.11 125.11,84.72 125.14,84.67 125.15,84.61 125.15,73.3 125.11,73.19 125,73.15 66.86,73.15 66.19,73.02 65.62,72.64 58.53,65.54 58.48,65.51 58.42,65.5 54.05,65.5 53.7,65.65 53.55,66 53.55,71.91 51.9,75.37 48.17,76.26 46.99,75.83 45.99,75.09 45.56,74.61 45.21,74.08 45.16,74.02 45.08,74 44.5,74 44.37,74.02 44.24,74.07 44.19,74.13 44.17,74.2 44.17,87.5 44.24,87.75 44.42,87.93 44.67,88 85.5,88 85.75,88.07 85.93,88.25 86,88.5 86,103.71 86.01,103.76 86.04,103.81 97.84,115.61 97.89,115.64 97.94,115.65 114,115.65 114.18,115.72 114.25,115.9 114.25,126.4 114.18,126.58 114,126.65 92.95,126.65 92.84,126.69 92.8,126.8 ; 44 cut-outs
GND_F on TOP: 183.42,5.92 184.05,6.56 184.1,6.59 184.16,6.6 201.74,6.6 201.8,6.59 201.85,6.56 202.48,5.92 204.03,4.37 204.41,4 205.51,3.26 206.81,3 237.73,3 239.89,3.77 241.07,5.74 242.17,7.83 244.26,8.93 246.23,10.11 247,12.27 247,65.23 246.23,67.39 244.26,68.57 241,72.5 244.26,76.43 246.23,77.61 247,79.77 247,118.97 246.43,120.85 244.9,122.11 242.31,123.18 239.02,124.54 238.67,124.69 238.65,124.7 238.63,124.72 235.44,127.9 235.41,127.95 235.4,128.01 235.4,143.5 235.55,143.85 235.9,144 248.01,144 248.71,143.71 249,143.01 249,134.49 249,131.76 249,127.25 249,127.24 249,124.51 249,124.5 249,72.68 249,72.5 249,72.32 248.99,5.25 249,5 248.99,4.75 248.99,2.01 248.7,1.3 247.99,1.01 245.25,1.01 245,1 244.75,1.01 168.15,1 82.25,1 82.14,1.04 82.1,1.15 82.1,4.61 83.42,5.92 84.05,6.56 84.1,6.59 84.16,6.6 119.54,6.6 120.91,6.89 122.04,7.69 126.09,8.85 128.93,5.74 130.11,3.77 132.27,3 179.09,3 180.39,3.26 181.49,4 ; 40 cut-outs
GND_F on BOTTOM: outline of 84 points within 82.1,1 249,144 ; 40 cut-outs
GND_F on CONDUCTIVE2, CONDUCTIVE3: 241,72.5 244.26,76.43 246.23,77.61 247,79.77 247,118.97 246.43,120.85 244.9,122.11 238.9,124.59 238.65,124.7 238.63,124.72 235.44,127.9 235.41,127.95 235.4,128.01 235.4,143.5 235.55,143.85 235.9,144 248.01,144 248.71,143.71 249,143.01 249,134.6 249,134.59 249,131.66 249,131.65 249,127.35 249,127.34 249,124.41 249,124.4 249,72.68 249,72.5 249,72.32 248.99,5.25 249,5 248.99,4.75 248.99,2.01 248.7,1.3 247.99,1.01 245.25,1.01 245,1 244.75,1.01 168.15,1 82.25,1 82.14,1.04 82.1,1.15 82.1,4.61 83.42,5.92 84.05,6.56 84.1,6.59 84.16,6.6 119.54,6.6 120.91,6.89 122.04,7.69 126.09,8.85 128.93,5.74 130.11,3.77 132.27,3 179.09,3 180.39,3.26 181.49,4 181.87,4.37 183.42,5.92 184.05,6.56 184.1,6.59 184.16,6.6 201.74,6.6 201.8,6.59 201.85,6.56 204.03,4.37 204.41,4 205.51,3.26 206.81,3 237.73,3 239.89,3.77 241.07,5.74 242.17,7.83 244.26,8.93 246.23,10.11 247,12.27 247,65.23 246.23,67.39 244.26,68.57 ; 40 cut-outs
VDD20_A on TOP: 6.8,80.1 6.71,80.13 6.66,80.21 6.33,80.4 6.2,80.75 6.2,82.25 6.36,82.64 6.75,82.8 8.25,82.8 8.64,82.64 8.8,82.25 8.8,81.5 8.84,81.39 8.95,81.35 9.1,81.35 9.21,81.39 9.25,81.5 9.25,85.65 9.29,85.76 9.4,85.8 10.45,85.8 10.56,85.76 10.6,85.65 10.6,84.26 10.59,84.2 10.56,84.16 10.25,83.85 10.25,80.25 10.21,80.14 10.1,80.1
VDD20_A on TOP: 8.6,121.76 8.59,121.7 8.56,121.66 7.5,120.6 7.5,117.03 8.48,116.05 9.75,116.05 10.14,115.89 10.3,115.5 10.3,113 10.23,112.75 10.05,112.57 9.8,112.5 4.9,112.5 4.79,112.54 4.75,112.65 4.75,116 4.04,116.71 4.01,116.75 4,116.81 4,122.95 4.07,123.2 4.25,123.38 4.5,123.45 8.45,123.45 8.56,123.41 8.6,123.3 ; 3 cut-outs
VDD20_A on TOP, BOTTOM: 2.06,30.8 1.97,30.82 1.92,30.83 1.83,30.88 1.8,30.98 1.73,31.03 1.7,31.12 1.7,35.3 1.77,35.55 1.95,35.73 2.2,35.8 3.9,35.8 4.15,35.73 4.33,35.55 4.4,35.3 4.4,31.2 4.33,30.95 4.15,30.77 3.9,30.7 2.28,30.7 2.24,30.71 2.2,30.72 2.15,30.75 ; 4 cut-outs
VDD20_A on BOTTOM: 6.75,80.2 6.36,80.36 6.2,80.75 6.2,82.25 6.36,82.64 6.75,82.8 8.25,82.8 8.64,82.64 8.8,82.25 8.8,80.75 8.64,80.36 8.25,80.2
VDD20_A on BOTTOM: 8.25,113.45 7.86,113.61 7.7,114 7.7,115.5 7.86,115.89 8.25,116.05 9.75,116.05 10.14,115.89 10.3,115.5 10.3,114 10.14,113.61 9.75,113.45
VDD20_A on CONDUCTIVE3: 2.4,35.25 2.45,35.48 2.58,35.67 3.1,36.2 3.1,36.9 3.14,37.01 3.25,37.05 4.45,37.05 4.56,37.01 4.6,36.9 4.6,31.2 4.53,30.95 4.35,30.77 4.1,30.7 2.55,30.7 2.44,30.74 2.4,30.85 2.4,31.67 2.39,31.74 2.38,31.81 2.35,32 2.38,32.19 2.39,32.26 2.4,32.33 ; 2 cut-outs
L1 on TOP, BOTTOM: 187.25,143.85 187.29,143.96 187.4,144 198.6,144 198.71,143.96 198.75,143.85 198.75,105.8 198.71,105.69 198.6,105.65 187.4,105.65 187.29,105.69 187.25,105.8 ; 24 cut-outs
L1 on CONDUCTIVE2, CONDUCTIVE3: 187.25,143.85 187.29,143.96 187.4,144 198.6,144 198.71,143.96 198.75,143.85 198.75,105.8 198.71,105.69 198.6,105.65 187.4,105.65 187.29,105.69 187.25,105.8 ; 24 cut-outs
L1F on TOP: outline of 111 points within 137.71,13.4 226.7,92.35 ; 32 cut-outs
L1F on BOTTOM: 218.95,63.3 218.91,63.19 218.8,63.15 214.9,63.15 214.79,63.19 214.75,63.3 214.75,69.4 214.79,69.51 214.9,69.55 218.8,69.55 218.91,69.51 218.95,69.4 ; 4 cut-outs
L1F on BOTTOM: 137.71,48.97 137.72,49.03 137.75,49.08 144.64,55.96 144.68,55.99 144.74,56 187.3,56 188.54,56.52 189.05,57.75 189.05,79.06 189.06,79.12 189.09,79.17 192.29,82.36 192.67,82.93 192.8,83.6 192.8,90.41 192.81,90.47 192.84,90.52 194.63,92.31 194.68,92.34 194.74,92.35 198.76,92.35 198.81,92.34 198.86,92.31 201.96,89.21 201.99,89.16 202,89.11 202,83.18 201.99,83.12 201.96,83.07 197.06,78.18 196.68,77.61 196.55,76.94 196.55,69.07 196.68,68.4 197.06,67.83 198.71,66.19 198.74,66.14 198.75,66.08 198.75,60.98 198.88,60.31 199.26,59.75 213.2,45.81 213.2,44.19 212.06,43.05 169.41,43.05 169.35,43.06 169.3,43.09 163.8,48.6 163.21,49.19 162.64,49.57 161.97,49.7 156.12,49.7 155.45,49.57 154.88,49.19 148.22,42.52 148.17,42.49 148.11,42.48 143.12,42.48 143.09,42.48 143.06,42.49 137.8,44.67 137.74,44.72 137.71,44.81 ; 24 cut-outs
L1F on BOTTOM: 196.9,16.93 196.9,13.55 196.86,13.44 196.75,13.4 191.6,13.4 191.49,13.44 191.45,13.55 191.45,17.9 191.49,18.01 191.6,18.05 195.78,18.05 ; 4 cut-outs
L1F on CONDUCTIVE2: outline of 95 points within 137.71,13.4 226.7,92.35 ; 32 cut-outs
L1F on CONDUCTIVE3: 218.95,63.3 218.91,63.19 218.8,63.15 214.9,63.15 214.79,63.19 214.75,63.3 214.75,69.4 214.79,69.51 214.9,69.55 218.8,69.55 218.91,69.51 218.95,69.4 ; 4 cut-outs
L1F on CONDUCTIVE3: 196.9,16.93 196.9,13.55 196.86,13.44 196.75,13.4 191.6,13.4 191.49,13.44 191.45,13.55 191.45,17.9 191.49,18.01 191.6,18.05 195.78,18.05 ; 4 cut-outs
L1F on CONDUCTIVE3: 137.71,48.97 137.72,49.03 137.75,49.08 144.64,55.96 144.68,55.99 144.74,56 187.3,56 188.54,56.52 189.05,57.75 189.05,79.06 189.06,79.12 189.09,79.17 192.29,82.36 192.67,82.93 192.8,83.6 192.8,90.41 192.81,90.47 192.84,90.52 194.63,92.31 194.68,92.34 194.74,92.35 198.76,92.35 198.81,92.34 198.86,92.31 201.96,89.21 201.99,89.16 202,89.11 202,83.18 201.99,83.12 201.96,83.07 197.06,78.18 196.68,77.61 196.55,76.94 196.55,69.07 196.68,68.4 197.06,67.83 198.71,66.19 198.74,66.14 198.75,66.08 198.75,60.98 198.88,60.31 199.26,59.75 211.84,47.17 213.2,45.81 213.2,44.19 212.06,43.05 169.41,43.05 169.35,43.06 169.3,43.09 164.55,47.85 164.55,47.85 163.21,49.19 162.64,49.57 161.97,49.7 156.12,49.7 155.45,49.57 154.88,49.19 148.22,42.52 148.17,42.49 148.11,42.48 143.12,42.48 143.09,42.48 143.06,42.49 137.8,44.67 137.74,44.72 137.71,44.81 ; 24 cut-outs
L1R on TOP: 141.87,23.08 141.84,23.08 141.81,23.09 122.91,30.92 122.32,31.16 120.68,31 119.9,29.55 119.9,14.61 119.88,14.53 119.82,14.48 119.01,13.99 118.25,13.43 118.21,13.41 118.16,13.4 114.6,13.4 114.49,13.44 114.45,13.55 114.45,38.5 114.52,38.75 114.7,38.93 114.95,39 118.27,39 118.3,39 118.33,38.99 140.24,29.91 140.57,29.81 140.91,29.78 150.85,29.78 150.96,29.73 151,29.63 151,25.07 150.97,24.98 150.91,24.93 146.44,23.08 ; 12 cut-outs
L1R on TOP: 32.7,1.15 32.66,1.04 32.55,1 20.05,1 19.94,1.04 19.9,1.15 19.9,14.85 19.94,14.96 20.05,15 22.19,15 23,14.95 23.81,15 32.55,15 32.66,14.96 32.7,14.85 ; 4 cut-outs
L1R on TOP, CONDUCTIVE2: 80,26.21 79.99,26.15 79.96,26.1 64.25,10.39 64.2,10.36 64.14,10.35 61.86,10.35 61.8,10.36 61.75,10.39 54.41,17.74 54.34,17.81 54.26,17.87 54.22,17.93 54.2,17.99 54.2,29.35 54.24,29.46 54.35,29.5 79.85,29.5 79.96,29.46 80,29.35 ; 4 cut-outs
L1R on BOTTOM: 114.45,17.76 114.49,17.86 114.6,17.91 116.84,17.91 116.84,17.91 118.86,17.91 118.92,17.89 118.97,17.86 119.86,16.97 119.89,16.92 119.9,16.87 119.9,14.61 119.88,14.53 119.82,14.48 119.01,13.99 118.25,13.43 118.21,13.41 118.16,13.4 114.6,13.4 114.49,13.44 114.45,13.55 ; 4 cut-outs
L1R on BOTTOM: 141.87,23.08 141.84,23.08 141.81,23.09 104.45,38.57 104.12,38.67 103.78,38.7 93.21,38.7 92.54,38.57 91.97,38.19 79.46,25.68 79.46,25.68 79.08,25.11 78.95,24.44 78.95,11.13 78.94,11.08 78.91,11.03 76.3,8.42 75.56,7.31 75.3,6.01 75.3,1.15 75.26,1.04 75.15,1 20.05,1 19.94,1.04 19.9,1.15 19.9,14.85 19.94,14.96 20.05,15 32.55,15 32.66,14.96 32.7,14.85 32.7,8.45 33.21,7.21 34.45,6.7 52.45,6.7 53.69,7.21 54.2,8.45 54.2,28.6 54.24,28.71 54.35,28.75 73.74,28.75 74.41,28.88 74.98,29.26 90.08,44.36 90.12,44.39 90.18,44.4 105.23,44.4 105.26,44.4 105.29,44.39 140.24,29.91 140.57,29.81 140.91,29.78 150.85,29.78 150.96,29.73 151,29.63 151,25.07 150.97,24.98 150.91,24.93 146.44,23.08 ; 16 cut-outs
L1R on CONDUCTIVE2: 141.87,23.08 141.84,23.08 141.81,23.09 122.91,30.92 122.32,31.16 120.68,31 119.9,29.55 119.9,14.61 119.89,14.55 119.86,14.5 119.82,14.48 119.01,13.99 118.25,13.43 118.23,13.42 118.2,13.41 118.16,13.4 114.6,13.4 114.49,13.44 114.45,13.55 114.45,38.5 114.52,38.75 114.7,38.93 114.95,39 118.27,39 118.3,39 118.33,38.99 140.24,29.91 140.57,29.81 140.91,29.78 150.85,29.78 150.96,29.73 151,29.63 151,25.07 150.97,24.98 150.91,24.93 146.44,23.08 ; 12 cut-outs
L1R on CONDUCTIVE3: 114.45,17.76 114.49,17.86 114.6,17.91 116.84,17.91 116.84,17.91 118.86,17.91 118.92,17.89 118.97,17.86 119.86,16.97 119.89,16.92 119.9,16.87 119.9,14.61 119.88,14.53 119.82,14.48 119.01,13.99 118.25,13.43 118.21,13.41 118.16,13.4 114.6,13.4 114.49,13.44 114.45,13.55 ; 4 cut-outs
L1R on CONDUCTIVE3: 141.87,23.08 141.84,23.08 141.81,23.09 104.45,38.57 104.12,38.67 103.78,38.7 93.21,38.7 92.54,38.57 91.97,38.19 79.46,25.68 79.46,25.68 79.08,25.11 78.95,24.44 78.95,11.13 78.94,11.08 78.91,11.03 76.3,8.42 75.56,7.31 75.3,6.01 75.3,1.15 75.26,1.04 75.15,1 20.05,1 19.94,1.04 19.9,1.15 19.9,14.85 19.94,14.96 20.05,15 32.55,15 32.66,14.96 32.7,14.85 32.7,8.45 33.21,7.21 34.45,6.7 52.45,6.7 53.69,7.21 54.2,8.45 54.2,28.6 54.24,28.71 54.35,28.75 73.74,28.75 74.41,28.88 74.98,29.26 90.08,44.36 90.12,44.39 90.18,44.4 105.23,44.4 105.26,44.4 105.29,44.39 140.24,29.91 140.57,29.81 140.91,29.78 150.85,29.78 150.96,29.73 151,29.63 151,25.07 150.97,24.98 150.91,24.93 146.44,23.08 ; 16 cut-outs
L2 on TOP: 202.25,143.85 202.29,143.96 202.4,144 213.6,144 213.71,143.96 213.75,143.85 213.75,122.54 213.88,121.87 214.26,121.3 216.72,118.85 218.4,117.17 218.91,116.66 218.94,116.61 218.95,116.55 218.95,105.8 218.91,105.69 218.8,105.65 202.4,105.65 202.29,105.69 202.25,105.8 ; 24 cut-outs
L2 on BOTTOM: 202.25,143.85 202.29,143.96 202.4,144 213.6,144 213.71,143.96 213.75,143.85 213.75,122.54 213.88,121.87 214.26,121.3 216.72,118.85 218.4,117.17 218.91,116.66 218.94,116.61 218.95,116.55 218.95,105.8 218.91,105.69 218.8,105.65 202.4,105.65 202.29,105.69 202.25,105.8 ; 24 cut-outs
L2 on CONDUCTIVE2, CONDUCTIVE3: 213.75,122.54 213.88,121.87 214.26,121.3 216.72,118.85 218.4,117.17 218.91,116.66 218.94,116.61 218.95,116.55 218.95,105.8 218.91,105.69 218.8,105.65 202.4,105.65 202.29,105.69 202.25,105.8 202.25,143.85 202.29,143.96 202.4,144 213.6,144 213.71,143.96 213.75,143.85 ; 24 cut-outs
L2F on TOP: 205.9,84.1 205.94,84.21 206.05,84.25 209.39,84.25 209.7,84.28 210.01,84.36 210.01,84.36 210.34,84.53 210.62,84.76 212.29,86.43 212.67,86.99 212.8,87.66 212.8,88.91 212.81,88.96 215.41,91.58 216.14,92.31 216.19,92.34 216.24,92.35 218.76,92.35 218.81,92.34 218.86,92.31 221.97,89.19 221.99,89.16 222,89.14 222,89.11 222,83.18 221.99,83.12 221.96,83.07 219.46,80.58 219.08,80.01 218.95,79.34 218.95,73.2 218.91,73.09 218.8,73.05 215.35,73.05 212.77,71.98 211.7,69.4 211.7,68.8 211.65,68.69 211.55,68.65 201.25,68.65 201.2,68.66 201.15,68.69 200.09,69.75 200.06,69.8 200.05,69.85 200.05,76.16 200.06,76.21 205.39,81.56 205.77,82.12 205.9,82.79 ; 16 cut-outs
L2F on TOP: 187.95,13.55 187.91,13.44 187.8,13.4 176.76,13.4 176.65,13.44 176.61,13.55 176.61,39.05 176.67,39.3 176.86,39.48 177.11,39.55 197.75,39.55 197.86,39.51 197.9,39.4 197.9,36.46 196.49,35.05 188.46,27.03 188.08,26.46 187.95,25.79 ; 12 cut-outs
L2F on TOP, CONDUCTIVE2: 219,28.05 218.99,28 218.96,27.95 212.06,21.05 204.15,21.05 204.04,21.09 204,21.2 204,22.59 204.01,22.65 204.04,22.69 211.3,29.95 211.35,29.98 211.4,29.99 218.85,29.99 218.96,29.95 219,29.84 ; 4 cut-outs
L2F on BOTTOM: 216.7,46.53 216.57,47.2 216.19,47.77 202.29,61.66 202.26,61.71 202.25,61.77 202.25,66.87 202.12,67.54 201.74,68.1 200.09,69.75 200.06,69.8 200.05,69.85 200.05,76.16 200.06,76.21 213.57,89.74 215.41,91.58 216.14,92.31 216.18,92.33 216.21,92.35 216.24,92.35 218.76,92.35 218.81,92.34 221.99,89.16 222,89.11 222,83.18 221.99,83.12 221.96,83.07 219.46,80.58 219.46,80.58 219.08,80.01 218.95,79.34 218.95,73.2 218.91,73.09 218.8,73.05 214.9,73.05 212.32,71.98 211.25,69.4 211.25,63.3 212.32,60.72 214.9,59.65 218.18,59.65 218.24,59.64 218.29,59.61 226.66,51.24 226.69,51.19 226.7,51.13 226.7,35.75 226.69,35.7 226.66,35.65 213.42,22.41 212.06,21.05 210.44,21.05 209.08,22.41 201.25,30.24 200.69,30.62 200.02,30.75 177.11,30.75 176.75,30.9 176.61,31.25 176.61,39.05 176.75,39.4 177.11,39.55 212.78,39.55 213.45,39.68 214.02,40.06 216.19,42.23 216.57,42.8 216.7,43.47 ; 28 cut-outs
L2F on CONDUCTIVE2: 187.95,13.55 187.91,13.44 187.8,13.4 176.76,13.4 176.65,13.44 176.61,13.55 176.61,39.05 176.67,39.3 176.86,39.48 177.11,39.55 197.75,39.55 197.86,39.51 197.9,39.4 197.9,36.46 196.49,35.05 188.46,27.03 188.08,26.46 187.95,25.79 ; 12 cut-outs
L2F on CONDUCTIVE2: 222,83.18 221.99,83.12 221.96,83.07 219.46,80.58 219.08,80.01 218.95,79.34 218.95,73.2 218.91,73.09 218.8,73.05 215.35,73.05 212.77,71.98 211.7,69.4 211.7,68.8 211.66,68.69 211.55,68.65 201.25,68.65 201.2,68.66 201.15,68.69 200.09,69.75 200.06,69.8 200.05,69.85 200.05,76.16 200.06,76.21 213.57,89.74 215.41,91.58 216.14,92.31 216.18,92.33 216.21,92.35 216.24,92.35 218.76,92.35 218.81,92.34 221.99,89.16 222,89.11 ; 16 cut-outs
L2F on CONDUCTIVE3: 216.7,46.53 216.57,47.2 216.19,47.77 202.29,61.66 202.26,61.71 202.25,61.77 202.25,66.87 202.12,67.54 201.74,68.1 200.09,69.75 200.06,69.8 200.05,69.85 200.05,76.16 200.06,76.21 213.57,89.74 215.41,91.58 216.14,92.31 216.19,92.34 216.24,92.35 218.76,92.35 218.81,92.34 221.99,89.16 222,89.11 222,83.18 221.99,83.12 221.96,83.07 219.46,80.58 219.46,80.58 219.08,80.01 218.95,79.34 218.95,73.2 218.91,73.09 218.8,73.05 214.9,73.05 212.32,71.98 211.25,69.4 211.25,63.3 212.32,60.72 214.9,59.65 218.18,59.65 218.24,59.64 226.66,51.24 226.69,51.19 226.7,51.13 226.7,35.75 226.69,35.7 226.66,35.65 213.42,22.41 212.06,21.05 210.44,21.05 209.08,22.41 201.25,30.24 200.69,30.62 200.02,30.75 177.11,30.75 176.75,30.9 176.61,31.25 176.61,39.05 176.75,39.4 177.11,39.55 212.78,39.55 213.45,39.68 214.02,40.06 216.19,42.23 216.57,42.8 216.7,43.47 ; 28 cut-outs
L2R on TOP: outline of 82 points within 37.2,13.4 163,53.6 ; 20 cut-outs
L2R on BOTTOM: 56.5,39 57.17,39.13 57.74,39.51 65.62,47.4 65.67,47.43 65.73,47.44 75.15,47.44 75.82,47.57 76.38,47.95 77.73,49.3 77.73,49.3 81.99,53.56 82.04,53.59 82.09,53.6 107.06,53.6 107.09,53.6 107.12,53.59 135.29,41.92 135.29,41.92 142.07,39.11 142.4,39.01 142.74,38.98 148.9,38.98 149.57,39.11 150.14,39.49 156.8,46.16 156.85,46.19 156.91,46.2 161.18,46.2 161.24,46.19 161.29,46.16 162.96,44.49 162.99,44.44 163,44.38 163,33.43 162.96,33.32 162.85,33.28 141.29,33.28 141.26,33.28 141.23,33.29 125.75,39.7 106.28,47.77 105.95,47.87 105.61,47.9 89.39,47.9 88.72,47.77 88.16,47.39 86.81,46.04 86.81,46.04 73.82,33.05 73.77,33.02 73.71,33.01 38.86,33.01 38.8,33.02 38.76,33.05 37.24,34.56 37.21,34.61 37.2,34.67 37.2,37.34 37.21,37.4 37.24,37.44 38.76,38.96 38.8,38.99 38.86,39 ; 16 cut-outs
L2R on BOTTOM: 96.84,17.91 96.84,17.91 99.26,17.91 99.31,17.9 99.35,17.88 99.64,17.61 99.88,17.29 99.89,17.26 99.9,17.21 99.9,13.55 99.86,13.44 99.75,13.4 93.95,13.4 93.84,13.44 93.8,13.55 93.8,17.76 93.84,17.86 93.95,17.91 ; 4 cut-outs
L2R on CONDUCTIVE2: outline of 81 points within 37.2,13.4 163,53.6 ; 20 cut-outs
L2R on CONDUCTIVE3: 96.84,17.91 96.84,17.91 99.26,17.91 99.31,17.9 99.35,17.88 99.64,17.61 99.88,17.29 99.89,17.26 99.9,17.21 99.9,13.55 99.86,13.44 99.75,13.4 93.95,13.4 93.84,13.44 93.8,13.55 93.8,17.76 93.84,17.86 93.95,17.91 ; 4 cut-outs
L2R on CONDUCTIVE3: 56.5,39 57.17,39.13 57.74,39.51 65.62,47.4 65.67,47.43 65.73,47.44 75.15,47.44 75.82,47.57 76.38,47.95 77.73,49.3 77.73,49.3 81.99,53.56 82.04,53.59 82.09,53.6 107.06,53.6 107.09,53.6 107.12,53.59 135.29,41.92 135.29,41.92 142.07,39.11 142.4,39.01 142.74,38.98 148.9,38.98 149.57,39.11 150.14,39.49 156.8,46.16 156.85,46.19 156.91,46.2 161.18,46.2 161.24,46.19 161.29,46.16 162.96,44.49 162.99,44.44 163,44.38 163,33.43 162.96,33.32 162.85,33.28 141.29,33.28 141.26,33.28 141.23,33.29 125.75,39.7 106.28,47.77 105.95,47.87 105.61,47.9 89.39,47.9 88.72,47.77 88.16,47.39 86.81,46.04 86.81,46.04 73.82,33.05 73.77,33.02 73.71,33.01 38.86,33.01 38.8,33.02 38.76,33.05 37.24,34.56 37.21,34.61 37.2,34.67 37.2,37.34 37.21,37.4 37.24,37.44 38.76,38.96 38.8,38.99 38.86,39 ; 16 cut-outs
L3 on BOTTOM: 217.25,143.85 217.29,143.96 217.4,144 228.45,144 228.56,143.96 228.6,143.85 228.6,126.54 228.86,125.24 229.6,124.13 234.32,119.41 234.71,119.07 235.15,118.8 235.28,118.73 235.42,118.67 238.27,117.49 240.11,116.73 240.17,116.68 240.2,116.59 240.2,105.8 240.16,105.69 240.05,105.65 222.6,105.65 222.49,105.69 222.45,105.8 222.45,117.34 222.32,118.01 221.94,118.57 221.94,118.57 217.29,123.22 217.26,123.27 217.25,123.32 ; 24 cut-outs
L3F on TOP: 230.2,51.92 230.07,52.59 229.69,53.15 222.49,60.35 222.46,60.4 222.45,60.45 222.45,78.56 222.46,78.61 222.49,78.66 225.39,81.56 225.77,82.12 225.9,82.79 225.9,84.1 225.94,84.21 226.05,84.25 229.39,84.25 230.06,84.38 230.62,84.76 232.29,86.43 232.67,86.99 232.8,87.66 232.8,88.91 232.81,88.96 235.41,91.58 236.14,92.31 236.19,92.34 236.24,92.35 240.05,92.35 240.16,92.31 240.2,92.2 240.2,82.27 240.18,82.19 240.12,82.13 239.26,81.65 238.46,81.09 237.38,80.16 236.44,79.09 234.47,70.11 240.12,62.87 240.18,62.81 240.2,62.73 240.2,14.77 240.18,14.69 240.12,14.63 237.36,12.64 235.37,9.88 235.31,9.82 235.23,9.8 208.28,9.8 208.23,9.81 208.18,9.84 205.62,12.4 205.62,12.4 204.51,13.14 203.21,13.4 200.9,13.4 200.55,13.55 200.4,13.9 200.4,17.05 200.55,17.4 200.9,17.55 212.78,17.55 213.45,17.68 214.02,18.06 214.02,18.06 229.69,33.73 229.69,33.73 230.07,34.3 230.2,34.97 ; 28 cut-outs
L3F on TOP, CONDUCTIVE2: 148.5,10.08 148.53,10.17 148.59,10.22 152.13,11.69 172.9,20.29 173.04,20.28 173.11,20.15 173.11,14.31 173.08,14.22 173.02,14.17 158.16,8.02 158.16,8.02 153.32,6.01 153.29,6 153.26,6 148.65,6 148.54,6.04 148.5,6.15 ; 4 cut-outs
L3F on BOTTOM: outline of 88 points within 148.5,6 240.2,92.35 ; 32 cut-outs
L3F on CONDUCTIVE2: 230.2,51.92 230.07,52.59 229.69,53.15 222.49,60.35 222.46,60.4 222.45,60.45 222.45,78.56 222.46,78.61 233.57,89.74 235.41,91.58 236.14,92.31 236.18,92.33 236.21,92.35 236.24,92.35 240.05,92.35 240.16,92.31 240.2,92.2 240.2,82.27 240.18,82.19 240.12,82.13 239.26,81.65 238.46,81.09 237.38,80.16 236.44,79.09 234.47,70.11 240.12,62.87 240.18,62.81 240.2,62.73 240.2,14.77 240.18,14.69 240.12,14.63 237.36,12.64 235.37,9.88 235.31,9.82 235.23,9.8 208.28,9.8 208.23,9.81 208.18,9.84 205.62,12.4 205.62,12.4 204.51,13.14 203.21,13.4 200.9,13.4 200.55,13.55 200.4,13.9 200.4,17.05 200.55,17.4 200.9,17.55 212.78,17.55 213.45,17.68 214.02,18.06 214.02,18.06 229.69,33.73 229.69,33.73 230.07,34.3 230.2,34.97 ; 28 cut-outs
L3F on CONDUCTIVE3: outline of 87 points within 148.5,6 240.2,92.35 ; 32 cut-outs
L3R on TOP: 75.3,1.15 75.26,1.04 75.15,1 36.35,1 36.25,1.04 36.2,1.15 36.2,10.87 36.21,10.9 36.3,12 36.2,13.11 36.2,13.14 36.2,14 36.2,14.85 36.24,14.96 36.35,15 46.19,15 47,14.95 47.81,15 52.14,15 52.19,14.99 52.24,14.96 59.84,7.36 60.4,6.98 61.07,6.85 64.93,6.85 65.6,6.98 66.16,7.36 85.26,26.46 85.31,26.49 85.36,26.5 86.79,26.5 86.85,26.49 86.9,26.46 90.26,23.1 90.29,23.05 90.3,22.99 90.3,13.55 90.26,13.44 90.15,13.4 82.69,13.4 81.39,13.14 80.28,12.4 76.3,8.42 75.56,7.31 75.3,6.01 ; 12 cut-outs
L3R on TOP, CONDUCTIVE2: 123.4,21.35 123.44,21.46 123.55,21.5 136.48,21.5 136.51,21.5 136.53,21.49 140.82,19.71 141.15,19.61 141.49,19.58 146.79,19.58 147.13,19.61 147.46,19.71 153.42,22.18 172.9,30.25 173.04,30.24 173.11,30.11 173.11,24.27 173.08,24.18 173.02,24.13 169.37,22.62 169.71,23.08 169.92,23.62 168.33,23.62 168.33,22.19 166.32,21.35 138.45,9.81 138.43,9.8 138.4,9.8 134.77,9.8 134.69,9.82 134.63,9.88 130.03,14.56 123.57,15.7 123.45,15.74 123.4,15.85 ; 3 cut-outs
L3R on TOP, CONDUCTIVE2: 110.95,21.65 110.91,21.54 110.8,21.5 103.55,21.5 103.44,21.54 103.4,21.65 103.4,24.02 103.27,24.69 102.89,25.26 97.39,30.75 97.36,30.8 97.35,30.86 97.35,35.05 97.39,35.16 97.5,35.2 103.4,35.2 103.43,35.2 103.46,35.19 110.86,32.12 110.92,32.07 110.95,31.99 ; 4 cut-outs
L3R on BOTTOM: 123.4,17.65 123.27,18.32 122.89,18.89 120.88,20.89 120.88,20.89 120.32,21.27 119.65,21.41 92.05,21.41 90.81,20.89 90.3,19.66 90.3,13.55 90.26,13.44 90.15,13.4 82.69,13.4 82.6,13.4 82.5,13.44 82.45,13.55 82.45,23.66 82.46,23.71 82.49,23.76 93.89,35.16 93.93,35.19 93.99,35.2 103.4,35.2 103.43,35.2 103.46,35.19 140.82,19.71 141.15,19.61 141.49,19.58 146.79,19.58 147.13,19.61 147.46,19.71 172.9,30.25 173.04,30.24 173.11,30.11 173.11,25.26 173.1,25.2 173.06,25.16 171.36,23.46 171.34,23.44 171.32,23.42 169.37,22.62 169.71,23.08 169.92,23.62 168.33,23.62 168.33,22.19 166.32,21.35 138.45,9.81 138.43,9.8 138.4,9.8 134.77,9.8 134.69,9.82 134.63,9.88 130.03,14.56 123.57,15.7 123.45,15.74 123.4,15.85 ; 15 cut-outs
L3R on CONDUCTIVE2: 75.3,1.15 75.26,1.04 75.15,1 36.35,1 36.25,1.04 36.2,1.15 36.2,11.9 36.2,14 36.2,14.85 36.24,14.96 36.35,15 52.14,15 52.19,14.99 52.24,14.96 59.84,7.36 60.4,6.98 61.07,6.85 64.93,6.85 65.6,6.98 66.16,7.36 85.26,26.46 85.31,26.49 85.36,26.5 86.79,26.5 86.85,26.49 86.9,26.46 90.26,23.1 90.29,23.05 90.3,22.99 90.3,13.55 90.26,13.44 90.15,13.4 82.69,13.4 81.39,13.14 80.28,12.4 76.3,8.42 75.56,7.31 75.3,6.01 ; 12 cut-outs
L3R on CONDUCTIVE3: 50.55,15 50.66,14.96 50.7,14.85 50.7,10.35 50.66,10.24 50.55,10.2 48.13,10.2 48.12,10.2 37.88,10.2 37.87,10.2 36.69,10.2 36.35,10.35 36.2,10.69 36.2,10.69 36.2,14.85 36.24,14.96 36.35,15 ; 2 cut-outs
L3R on CONDUCTIVE3: 123.4,17.65 123.27,18.32 122.89,18.89 120.88,20.89 120.88,20.89 120.32,21.27 119.65,21.41 92.05,21.41 90.81,20.89 90.3,19.66 90.3,13.55 90.26,13.44 90.15,13.4 82.69,13.4 82.6,13.4 82.5,13.44 82.45,13.55 82.45,23.66 82.46,23.71 82.49,23.76 93.89,35.16 93.93,35.19 93.99,35.2 103.4,35.2 103.43,35.2 103.46,35.19 140.82,19.71 141.15,19.61 141.49,19.58 146.79,19.58 147.13,19.61 147.46,19.71 172.9,30.25 173.04,30.24 173.11,30.11 173.11,25.26 173.1,25.2 173.06,25.16 171.36,23.46 171.34,23.44 171.32,23.42 169.37,22.62 169.71,23.08 169.92,23.62 168.33,23.62 168.33,22.19 166.32,21.35 138.45,9.81 138.43,9.8 138.4,9.8 134.77,9.8 134.69,9.82 134.63,9.88 130.03,14.56 123.57,15.7 123.45,15.74 123.4,15.85 ; 15 cut-outs
M on TOP: 92.69,91.98 92.66,92.03 92.65,92.09 92.65,99.91 92.66,99.97 92.69,100.02 93.98,101.31 94.03,101.34 94.09,101.35 95.99,101.35 96.05,101.34 96.09,101.31 97.36,100.04 97.39,100 97.4,99.94 97.4,92.06 97.39,92 97.36,91.96 96.09,90.69 96.05,90.66 95.99,90.65 94.09,90.65 94.03,90.66 93.98,90.69 ; 8 cut-outs
M on TOP: 161.31,115.22 161.34,115.18 161.35,115.12 161.35,74.88 161.34,74.82 161.31,74.78 159.72,73.19 159.68,73.16 159.62,73.15 148.5,73.15 147.5,74.15 147.5,115.85 148.5,116.85 159.62,116.85 159.68,116.84 159.72,116.81 ; 8 cut-outs
M on BOTTOM: 94.09,90.65 94.03,90.66 93.98,90.69 92.69,91.98 92.66,92.03 92.65,92.09 92.65,99.91 92.66,99.97 92.69,100.02 93.98,101.31 94.03,101.34 94.09,101.35 123.4,101.35 124.07,101.48 124.64,101.86 128.14,105.36 128.52,105.93 128.65,106.6 128.65,115.12 128.66,115.18 128.69,115.22 130.28,116.81 130.32,116.84 130.38,116.85 159.62,116.85 159.68,116.84 159.72,116.81 161.31,115.22 161.34,115.18 161.35,115.12 161.35,74.88 161.34,74.82 161.31,74.78 159.72,73.19 159.68,73.16 159.62,73.15 128.8,73.15 128.69,73.19 128.65,73.3 128.65,85.4 128.52,86.07 128.14,86.64 124.64,90.14 124.64,90.14 124.07,90.52 123.4,90.65 ; 24 cut-outs
M on CONDUCTIVE2, CONDUCTIVE3: 94.09,90.65 94.03,90.66 93.98,90.69 92.69,91.98 92.66,92.03 92.65,92.09 92.65,99.91 92.66,99.97 92.69,100.02 93.98,101.31 94.03,101.34 94.09,101.35 123.4,101.35 124.07,101.48 124.64,101.86 128.14,105.36 128.52,105.93 128.65,106.6 128.65,115.12 128.66,115.18 128.69,115.22 130.28,116.81 130.32,116.84 130.38,116.85 159.62,116.85 159.68,116.84 159.72,116.81 161.31,115.22 161.34,115.18 161.35,115.12 161.35,74.88 161.34,74.82 161.31,74.78 159.72,73.19 159.68,73.16 159.62,73.15 128.8,73.15 128.69,73.19 128.65,73.3 128.65,85.4 128.52,86.07 128.14,86.64 124.64,90.14 124.64,90.14 124.07,90.52 123.4,90.65 ; 24 cut-outs
RDIS on TOP: 185.85,88.3 185.74,88.34 185.7,88.45 185.7,101.65 185.77,101.9 185.95,102.08 186.2,102.15 228.8,102.15 229.05,102.08 229.23,101.9 229.3,101.65 229.3,88.45 229.26,88.34 229.15,88.3 226.05,88.3 225.94,88.34 225.9,88.45 225.9,89.49 225.85,89.9 225.7,90.31 225.7,90.34 225.7,90.42 220.78,95.34 220.27,95.85 214.73,95.85 214.22,95.34 209.3,90.42 209.3,88.45 209.26,88.34 209.15,88.3 206.05,88.3 205.94,88.34 205.9,88.45 205.9,89.49 205.85,89.9 205.7,90.31 205.7,90.34 205.7,90.42 200.78,95.34 200.21,95.72 199.54,95.85 193.22,95.85 189.3,91.93 189.3,88.45 189.26,88.34 189.15,88.3
RDIS on BOTTOM, CONDUCTIVE2, CONDUCTIVE3: 186.5,89.95 185.93,90.18 185.7,90.75 185.7,101.65 185.77,101.9 185.95,102.08 186.2,102.15 228.8,102.15 229.05,102.08 229.23,101.9 229.3,101.65 229.3,90.75 229.24,90.45 228.81,90.01 228.51,89.95 226.49,89.95 226.19,90.01 220.78,95.34 220.27,95.85 214.73,95.85 214.22,95.34 208.81,90.01 208.51,89.95 206.49,89.95 206.19,90.01 200.78,95.34 200.21,95.72 199.54,95.85 193.22,95.85 189.3,91.93 189.3,90.74 189.06,90.18 188.5,89.95
SIGN00122 on TOP: 30.6,87.5 30.75,87.85 31.1,88 42.67,88 43.02,87.85 43.17,87.5 43.17,57.77 45.79,55.15 46.34,54.78 47.02,54.64 54.2,54.64 54.31,54.6 54.35,54.49 54.35,48.25 55.96,46.64 55.99,46.6 56,46.54 56,42.81 55.99,42.75 55.96,42.71 55.79,42.54 55.75,42.51 55.69,42.5 38.07,42.5 37.41,42.37 36.84,41.99 34.21,39.36 33.83,38.79 33.7,38.12 33.7,33.87 33.83,33.21 34.21,32.64 36.84,30.01 37.41,29.63 38.08,29.5 50.55,29.5 50.66,29.46 50.7,29.35 50.7,18.75 50.69,18.68 50.68,18.61 50.63,18.53 50.54,18.5 29.65,18.5 29.54,18.54 29.5,18.65 29.5,72.13 29.51,72.19 29.54,72.24 29.9,72.63 30.14,73 30.48,73.82 30.6,74.7 ; 20 cut-outs
